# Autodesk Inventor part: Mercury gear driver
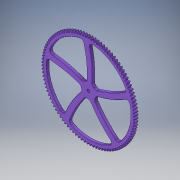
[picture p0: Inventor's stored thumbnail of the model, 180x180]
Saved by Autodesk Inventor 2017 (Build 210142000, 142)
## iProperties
Created: 2016-05
Part Number: Mercury gear driver
Material: Generic
Document SubType Name: Modeling
Designer: Stan
Density: 1 g/cm^3
Appearance: Violet
Author: Stan
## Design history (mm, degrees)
sketch "Sketch1"
  geometry: A1 r 20.677 centre (-14.735, -90.212) between (3.897, -99.179) and (5.255, -95.496); A2 r 20.677 centre (25.926, -87.654) between (6.755, -95.402) and (8.564, -98.885); A3 r 20.677 centre (-9.042, -90.96) between (10.117, -98.738) and (11.241, -94.978); A4 r 20.677 centre (31.379, -85.853) between (12.732, -94.79) and (14.757, -98.152); A5 r 20.677 centre (-3.313, -91.348) between (16.296, -97.908) and (17.183, -94.085); A6 r 20.677 centre (36.707, -83.714) between (18.659, -93.803) and (20.89, -97.032); A7 r 20.677 centre (2.43, -91.376) between (22.412, -96.692) and (23.057, -92.82); A8 r 20.677 centre (41.891, -81.244) between (24.512, -92.446) and (26.942, -95.529); A9 r 20.677 centre (8.162, -91.043) between (28.439, -95.094) and (28.839, -91.189); A10 r 20.677 centre (46.91, -78.453) between (30.268, -90.725) and (32.887, -93.649); A11 r 20.677 centre (13.863, -90.351) between (34.354, -93.121) and (34.508, -89.198); A12 r 20.677 centre (51.744, -75.353) between (35.905, -88.645) and (38.702, -91.399); A13 r 20.677 centre (19.509, -89.302) between (40.133, -90.78) and (40.041, -86.856); A14 r 20.677 centre (56.373, -71.955) between (41.4, -86.216) and (44.365, -88.788); A15 r 20.677 centre (25.078, -87.901) between (45.754, -88.081) and (45.416, -84.17); A16 r 20.677 centre (60.78, -68.273) between (46.732, -83.446) and (49.853, -85.827); A17 r 20.677 centre (30.547, -86.153) between (51.195, -85.034) and (50.611, -81.152); A18 r 20.677 centre (64.947, -64.322) between (51.88, -80.347) and (55.143, -82.528); A19 r 20.677 centre (35.897, -84.064) between (56.433, -81.652) and (55.607, -77.814); A20 r 20.677 centre (68.857, -60.117) between (56.822, -76.931) and (60.216, -78.903); A21 r 20.677 centre (41.104, -81.645) between (61.448, -77.947) and (60.383, -74.169); A22 r 20.677 centre (72.496, -55.675) between (61.541, -73.211) and (65.052, -74.966); A23 r 20.677 centre (46.15, -78.903) between (66.221, -73.935) and (64.921, -70.231); A24 r 20.677 centre (75.849, -51.013) between (66.016, -69.203) and (69.631, -70.733); A25 r 20.677 centre (51.013, -75.849) between (70.733, -69.631) and (69.203, -66.016); A26 r 20.677 centre (78.903, -46.15) between (70.231, -64.921) and (73.935, -66.221); A27 r 20.677 centre (55.675, -72.496) between (74.966, -65.052) and (73.211, -61.541); A28 r 20.677 centre (81.645, -41.104) between (74.169, -60.383) and (77.947, -61.448); A29 r 20.677 centre (60.117, -68.857) between (78.903, -60.216) and (76.931, -56.822); A30 r 20.677 centre (84.064, -35.897) between (77.814, -55.607) and (81.652, -56.433); A31 r 20.677 centre (64.322, -64.947) between (82.528, -55.143) and (80.347, -51.88); A32 r 20.677 centre (86.153, -30.547) between (81.152, -50.611) and (85.034, -51.195); A33 r 20.677 centre (68.273, -60.78) between (85.827, -49.853) and (83.446, -46.732); A34 r 20.677 centre (87.901, -25.078) between (84.17, -45.416) and (88.081, -45.754); A35 r 20.677 centre (71.955, -56.373) between (88.788, -44.365) and (86.216, -41.4); A36 r 20.677 centre (89.302, -19.509) between (86.856, -40.041) and (90.78, -40.133); A37 r 20.677 centre (75.353, -51.744) between (91.399, -38.702) and (88.645, -35.905); A38 r 20.677 centre (90.351, -13.863) between (89.198, -34.508) and (93.121, -34.354); A39 r 20.677 centre (78.453, -46.91) between (93.649, -32.887) and (90.725, -30.268); A40 r 20.677 centre (91.043, -8.162) between (91.189, -28.839) and (95.094, -28.439); A41 r 20.677 centre (81.244, -41.891) between (95.529, -26.942) and (92.446, -24.512); A42 r 20.677 centre (91.376, -2.43) between (92.82, -23.057) and (96.692, -22.412); A43 r 20.677 centre (83.714, -36.707) between (97.032, -20.89) and (93.803, -18.659); A44 r 20.677 centre (91.348, 3.313) between (94.085, -17.183) and (97.908, -16.296); A45 r 20.677 centre (85.853, -31.379) between (98.152, -14.757) and (94.79, -12.732); A46 r 20.677 centre (90.96, 9.042) between (94.978, -11.241) and (98.738, -10.117); A47 r 20.677 centre (87.654, -25.926) between (98.885, -8.564) and (95.402, -6.755); A48 r 20.677 centre (90.212, 14.735) between (95.496, -5.255) and (99.179, -3.897); A49 r 20.677 centre (89.109, -20.371) between (99.228, -2.338) and (95.638, -0.751); A50 r 20.677 centre (89.109, 20.371) between (95.638, 0.751) and (99.228, 2.338); A51 r 20.677 centre (90.212, -14.735) between (99.179, 3.897) and (95.496, 5.255); A52 r 20.677 centre (87.654, 25.926) between (95.402, 6.755) and (98.885, 8.564); A53 r 20.677 centre (90.96, -9.042) between (98.738, 10.117) and (94.978, 11.241); A54 r 20.677 centre (85.853, 31.379) between (94.79, 12.732) and (98.152, 14.757); A55 r 20.677 centre (91.348, -3.313) between (97.908, 16.296) and (94.085, 17.183); A56 r 20.677 centre (83.714, 36.707) between (93.803, 18.659) and (97.032, 20.89); A57 r 20.677 centre (91.376, 2.43) between (96.692, 22.412) and (92.82, 23.057); A58 r 20.677 centre (81.244, 41.891) between (92.446, 24.512) and (95.529, 26.942); A59 r 20.677 centre (91.043, 8.162) between (95.094, 28.439) and (91.189, 28.839); A60 r 20.677 centre (78.453, 46.91) between (90.725, 30.268) and (93.649, 32.887); A61 r 20.677 centre (90.351, 13.863) between (93.121, 34.354) and (89.198, 34.508); A62 r 20.677 centre (75.353, 51.744) between (88.645, 35.905) and (91.399, 38.702); A63 r 20.677 centre (89.302, 19.509) between (90.78, 40.133) and (86.856, 40.041); A64 r 20.677 centre (71.955, 56.373) between (86.216, 41.4) and (88.788, 44.365)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; 1 further point
  constraints: 800 point on circle, 400 centre point, 4 horizontal alignment, 4 vertical alignment, 1192 other
  dimensions: "d0" = 0 dimension on point (0, 0); "d1" = 0 dimension on point (0, 0)
extrude "Extrusion1" new body sketch "Sketch1" distance "d2" = 6.35; taper "d3" = 0 deg
sketch "Sketch4"
  geometry: A1 r 216.386 centre (-208.485, 32.382) between (7.134, 14.182) and (0.39, 88.899); A2 r 216.386 centre (-219.683, 27.015) between (-3.606, 15.46) and (-12.09, 88.074); A3 r 216.386 centre (-95.222, -188.274) between (-11.283, 11.167) and (-84.428, 27.842); A4 r 216.386 centre (-93.579, -200.582) between (-15.818, 1.348) and (-87.499, 15.718); A5 r 216.386 centre (149.634, -148.742) between (-14.107, -7.28) and (-52.569, -71.692); A6 r 216.386 centre (161.848, -150.982) between (-6.17, -14.627) and (-41.987, -78.36); A7 r 216.386 centre (187.701, 96.347) between (2.564, -15.667) and (51.938, -72.15); A8 r 216.386 centre (193.606, 107.27) between (12.004, -10.388) and (61.55, -64.147); A9 r 216.386 centre (-33.628, 208.287) between (15.692, -2.403) and (84.669, 27.101); A10 r 216.386 centre (-42.192, 217.279) between (13.589, 8.207) and (80.027, 38.715); A11 r 88.9 centre (0, 0) between (-12.09, 88.074) and (-84.428, 27.842); A12 r 88.9 centre (0, 0) between (-87.499, 15.718) and (-52.569, -71.692); A13 r 15.875 centre (0, 0) between (-15.818, 1.348) and (-14.107, -7.28); A14 r 15.875 centre (0, 0) between (-3.606, 15.46) and (-11.283, 11.167); A15 r 15.875 centre (0, 0) between (13.589, 8.207) and (7.134, 14.182); A16 r 15.875 centre (0, 0) between (-6.17, -14.627) and (2.564, -15.667); A17 r 15.875 centre (0, 0) between (12.004, -10.388) and (15.692, -2.403); A18 r 88.9 centre (0, 0) between (-41.987, -78.36) and (51.938, -72.15); A19 r 88.9 centre (0, 0) between (61.55, -64.147) and (84.669, 27.101); A20 r 88.9 centre (0, 0) between (80.027, 38.715) and (0.39, 88.899); 1 further point
  constraints: 40 point on circle, 20 centre point, 2 coincident, 41 other
  dimensions: "d21" = 360 deg dimension on point (0, 0) A1.centre (derived)
extrude "Extrusion4" cut sketch "Sketch4" distance "d23" = 6.35; taper "d24" = 0 deg
sketch "Sketch5"
  geometry: C1 r 3.175 at (0, 0); 1 further point
  constraints: 1 centre point, 1 coincident
  dimensions: "d25" = 6.35 diameter of C1
extrude "Extrusion5" cut sketch "Sketch5" distance "d26" = 6.35; taper "d27" = 0 deg
fillet "Fillet3" dims "d28" = 6.35
fillet "Fillet4" dims "d29" = 0.79375
fillet "Fillet5" dims "d30" = 0.79375
fillet "Fillet6" dims "d31" = 0.762
fillet "Fillet7" dims "d32" = 0.762
fillet "Fillet8" dims "d33" = 0.762
fillet "Fillet9" dims "d34" = 0.762
fillet "Fillet10" dims "d35" = 0.762
fillet "Fillet11" dims "d36" = 0.762
fillet "Fillet12" dims "d37" = 0.762
fillet "Fillet13" dims "d38" = 0.762
body "Solid1"
other parameters: "d0" = 0, "d1" = 0, "d4" = 180.975, "d5" = 25.4, "d17" = 177.8, "d18" = 31.75
